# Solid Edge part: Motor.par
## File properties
Author: CADCIM
Template: NORMENG.PAR
Last saved by: CADCIM
Revision: 9
Application: Solid Edge
Accuracy: 0.99
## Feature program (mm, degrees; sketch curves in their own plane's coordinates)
sketch for "unnamed Protrusion 1" plane through (0, 0, 0) normal (0, -1, 0) x-axis (1, 0, 0)
  line (-152.4, 0) -> (152.4, 0)
  line (152.4, 0) -> (83.1942, 183.7359)
  line (-152.4, 0) -> (-83.1942, 183.7359)
  dimension (linear) = 152.4
extrude "unnamed Protrusion 1" add finite 165.1 along -normal
sketch for "ExtrudedProtrusion_2" plane through (0, 165.1, 120.65) normal (0, 1, 0) x-axis (-1, 0, 0)
  circle centre (0, 31.75) radius 88.9
extrude "ExtrudedProtrusion_2" add finite 57.15 along +normal
sketch for "ExtrudedProtrusion_3" plane through (0, 222.25, 152.4) normal (0, 1, 0) x-axis (-1, 0, 0)
  circle centre (0, 0) radius 127
extrude "ExtrudedProtrusion_3" add finite 12.7 along +normal
sketch for "ExtrudedProtrusion_4" plane through (0, 222.25, 152.4) normal (0, -1, 0) x-axis (1, 0, 0)
  line (-76.2, 25.4) -> (76.2, 25.4)
  line (76.2, 25.4) -> (76.2, 152.4)
  line (76.2, 152.4) -> (-76.2, 152.4)
  line (-76.2, 152.4) -> (-76.2, 25.4)
  dimension (linear) = 76.2
  dimension (linear) = 76.2
extrude "ExtrudedProtrusion_4" add finite 203.2 along +normal
sketch for "unnamed Cutout 1" plane through (0, 19.05, 251.4953) normal (0, -1, 0) x-axis (1, 0, 0)
  line (-76.2, 41.8747) -> (-63.5, 41.8747)
  line (-63.5, 41.8747) -> (-63.5, 30.4447)
  line (-63.5, 30.4447) -> (-76.2, 30.4447)
  line (-76.2, 30.4447) -> (-76.2, 41.8747)
  dimension (linear) = 76.2
  dimension (linear) = 76.2
  dimension (linear) = 63.5
extrude "unnamed Cutout 1" cut along +normal
pattern "unnamed Pattern 1" of "unnamed Cutout 1"
extrude "unnamed Cutout 2" cut
extrude "unnamed Cutout 3" cut
extrude "unnamed Cutout 4" cut
extrude "unnamed Cutout 5" cut
extrude "unnamed Cutout 6" cut
extrude "unnamed Cutout 7" cut
extrude "unnamed Cutout 8" cut
sketch for "Hole_1" plane through (0, 234.95, 152.4) normal (0, 1, 0) x-axis (-1, 0, 0)
  hole centre (0, 0) bore radius 76.2
hole "Hole_1" diameter 152.4 finite
sketch for "Hole_2" plane through (0, 0, 120.65) normal (0, -1, 0) x-axis (1, 0, 0)
  hole centre (0, 31.75) bore radius 19.05
hole "Hole_2" diameter 38.1 through
sketch for "Hole_3" plane through (0, 234.95, 152.4) normal (0, 1, 0) x-axis (-1, 0, 0)
  hole centre (0, -107.95) bore radius 9.525
hole "Hole_3" diameter 19.05 through
pattern "unnamed Pattern 2" of "Hole_3"
pattern "unnamed Pattern 3"
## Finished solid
Body 1: solid body, 60 faces, 151 edges, 90 vertices.
  Faces by surface: plane 53, cylinder 7
  Edges by curve: line 126, circle 25
Bounding box of the edges (mm): 304.800 x 234.950 x 304.800, from (-152.4, 0, 0) to (152.4, 234.95, 304.8).
Cylindrical faces by radius (mm): R9.525 x3, R19.05 x1, R76.2 x1, R88.9 x1, R127 x1
Planar faces by outward normal: +x 9, +y 8, +z 9, -x 9, -y 7, -z 9, oblique 2
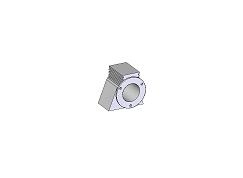
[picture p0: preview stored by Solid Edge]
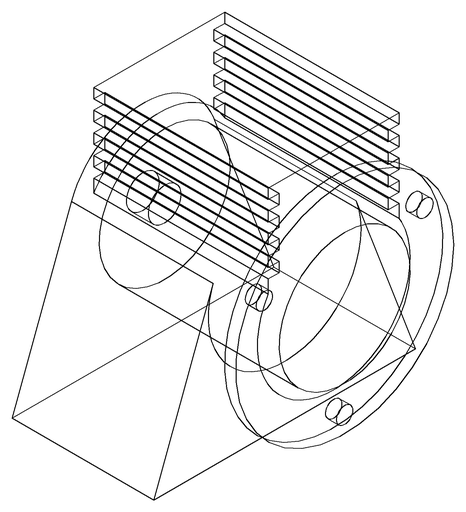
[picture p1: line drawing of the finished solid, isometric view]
